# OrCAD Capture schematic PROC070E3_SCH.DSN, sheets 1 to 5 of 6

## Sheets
1 06. HARDWARE SCHEMATICS: title: HARDWARE SCHEMATICS; rev: E3; note: PROC066
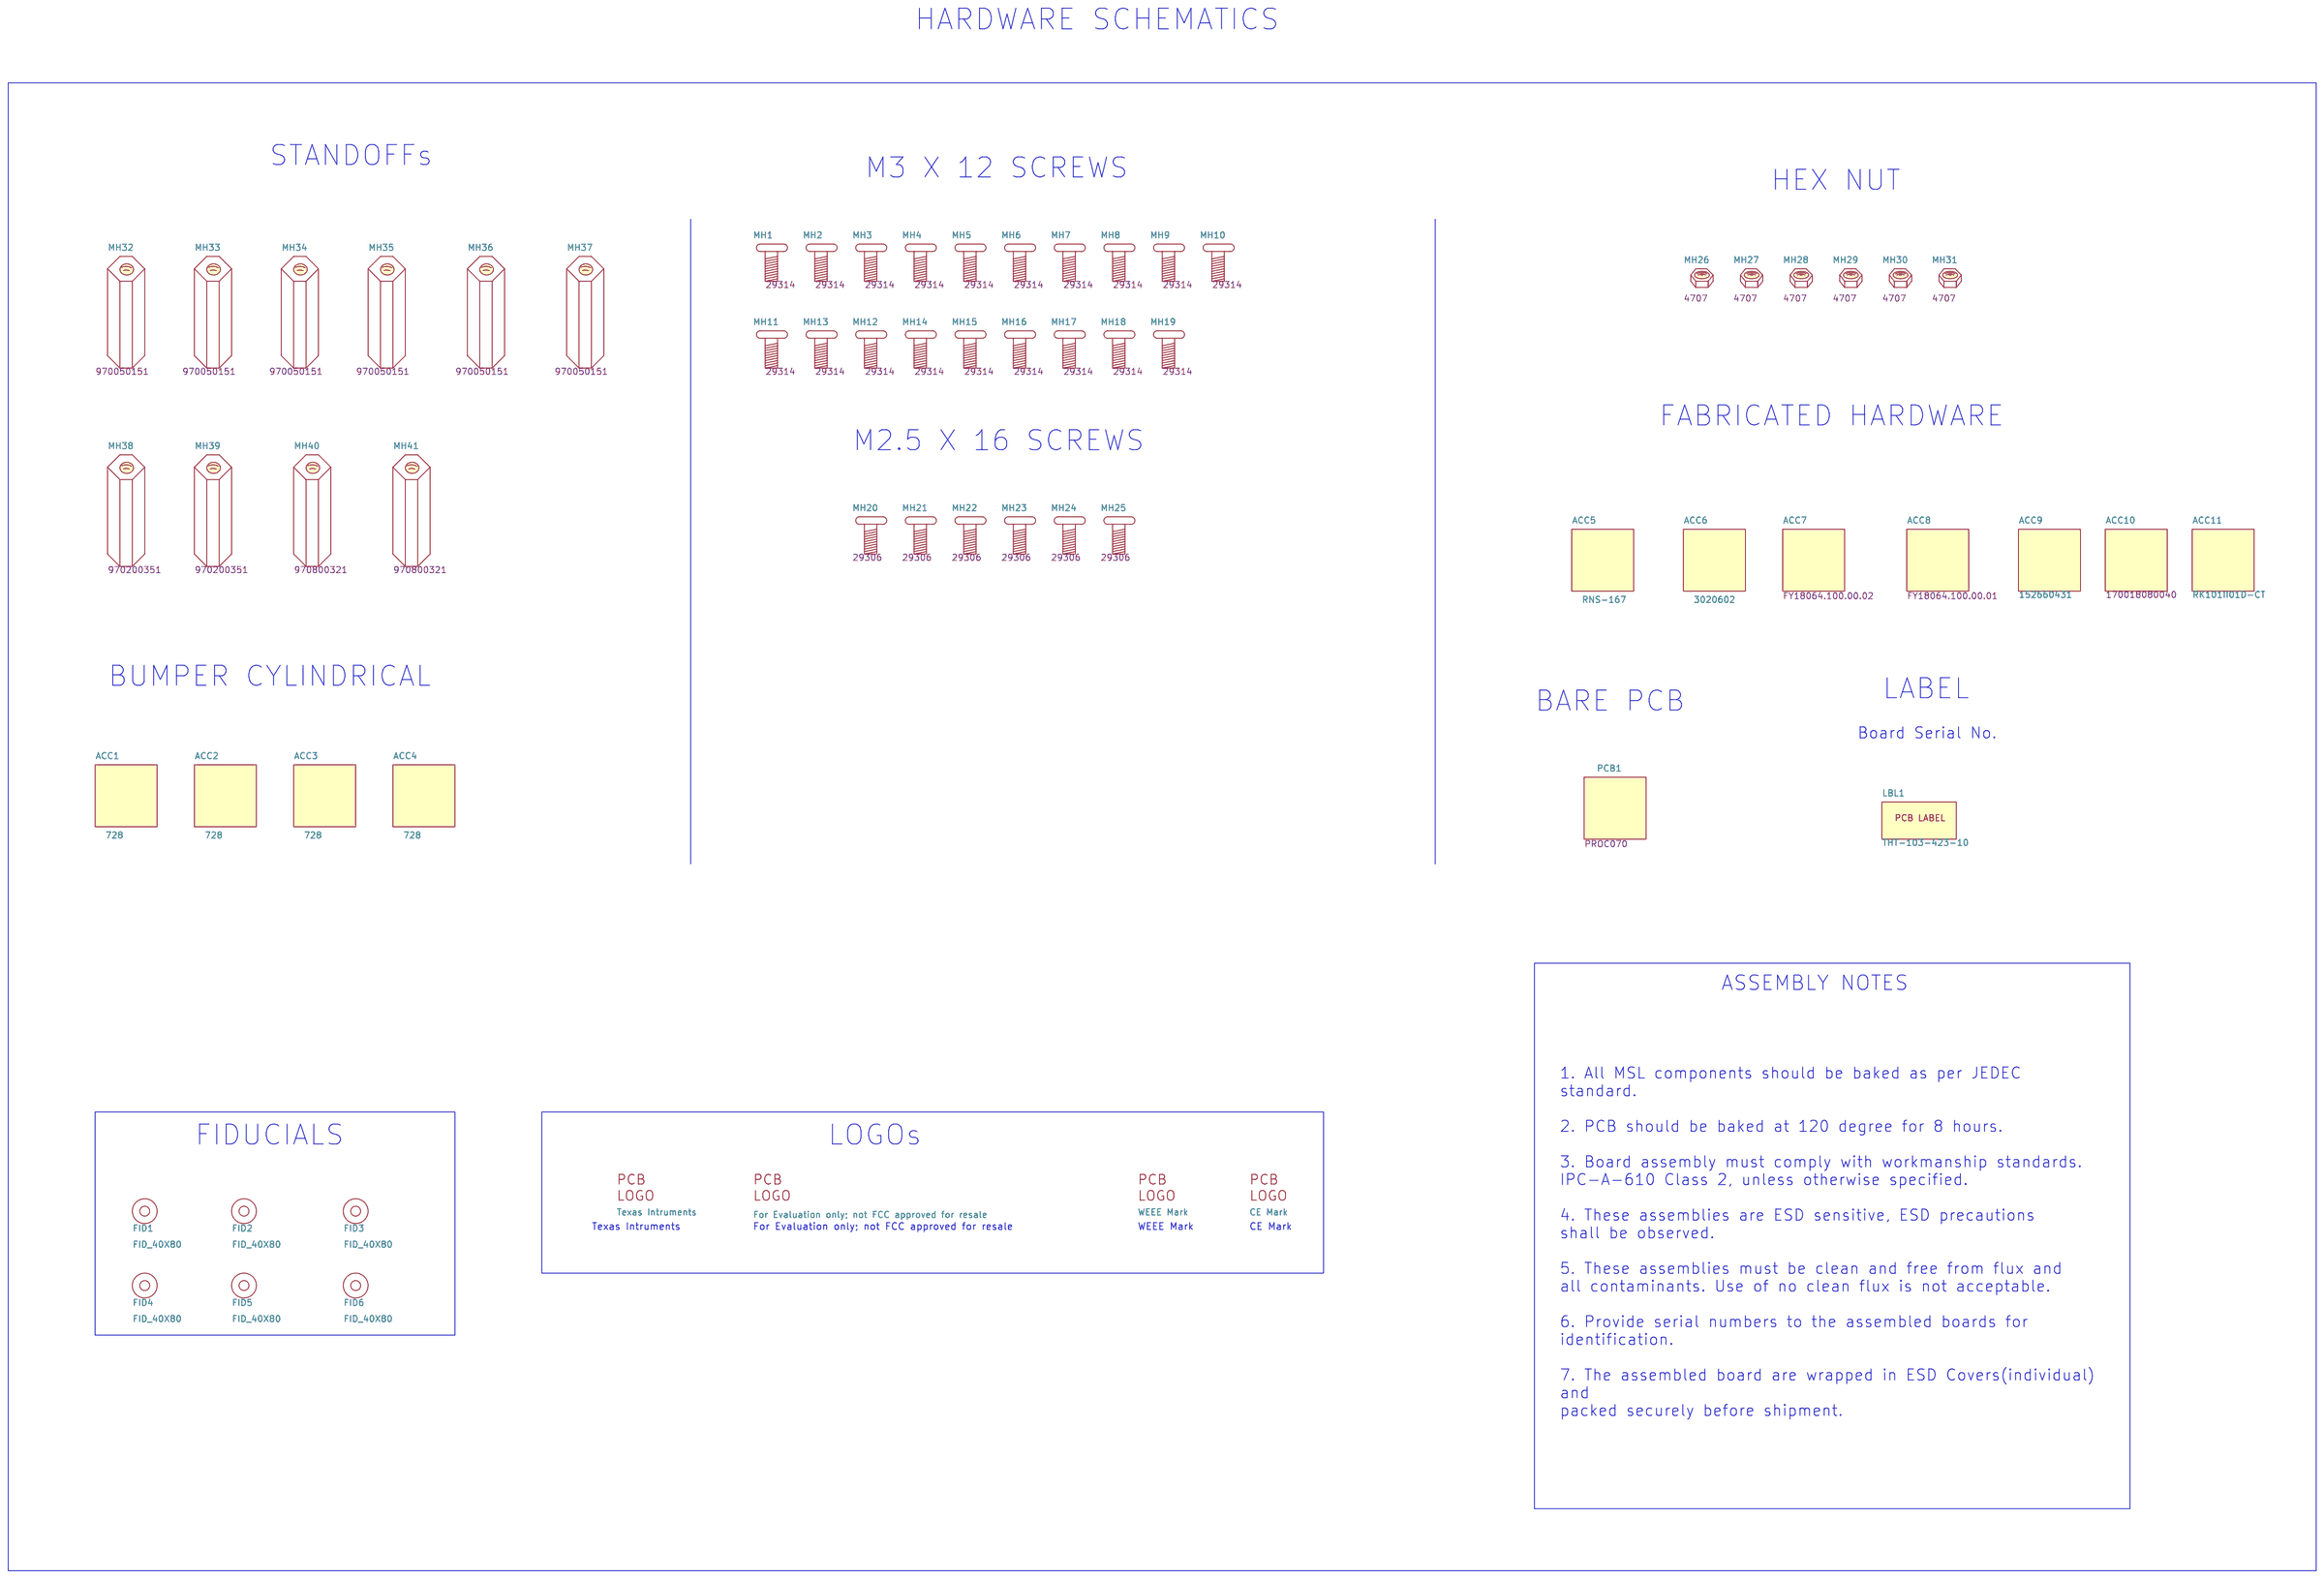
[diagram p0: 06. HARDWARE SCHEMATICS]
2 03. BLOCK DIAGRAM: title: BLOCK DIAGRAM
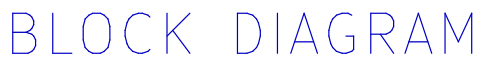
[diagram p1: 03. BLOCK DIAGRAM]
3 02. REVISION HISTORY: title: VERSION HISTORY
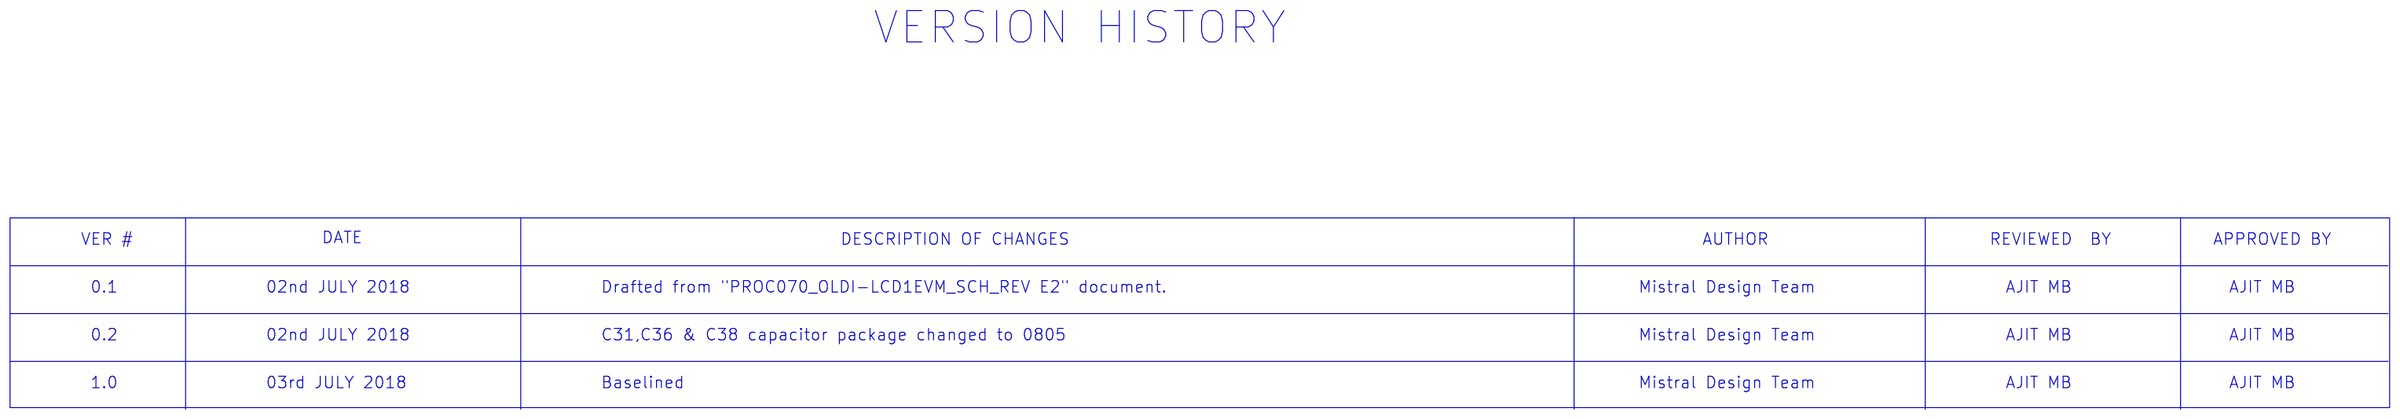
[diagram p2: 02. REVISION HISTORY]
4 01. TABLE OF CONTENTS: title: TABLE OF CONTENTS
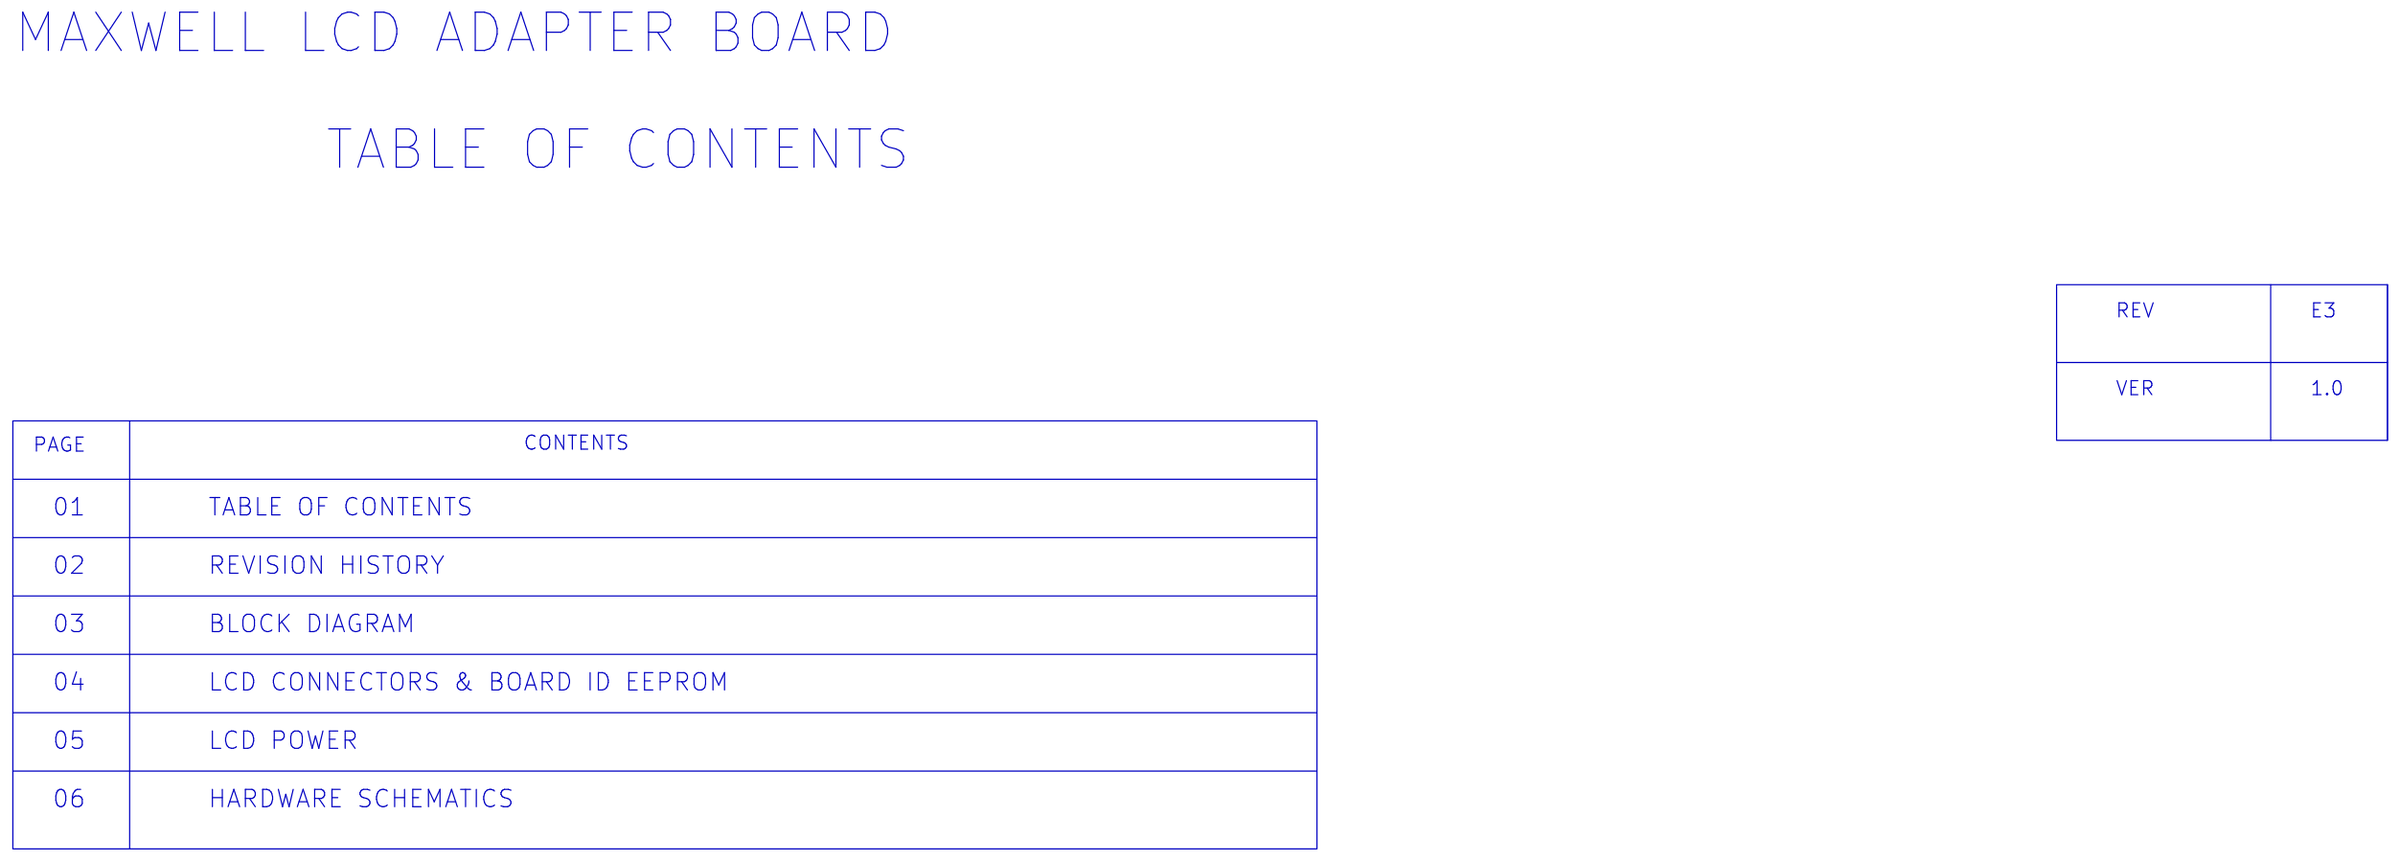
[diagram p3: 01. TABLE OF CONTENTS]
5 04. LCD CONNECTOR & EEPROM: size C; title: LCD CONNECTOR & EEPROM
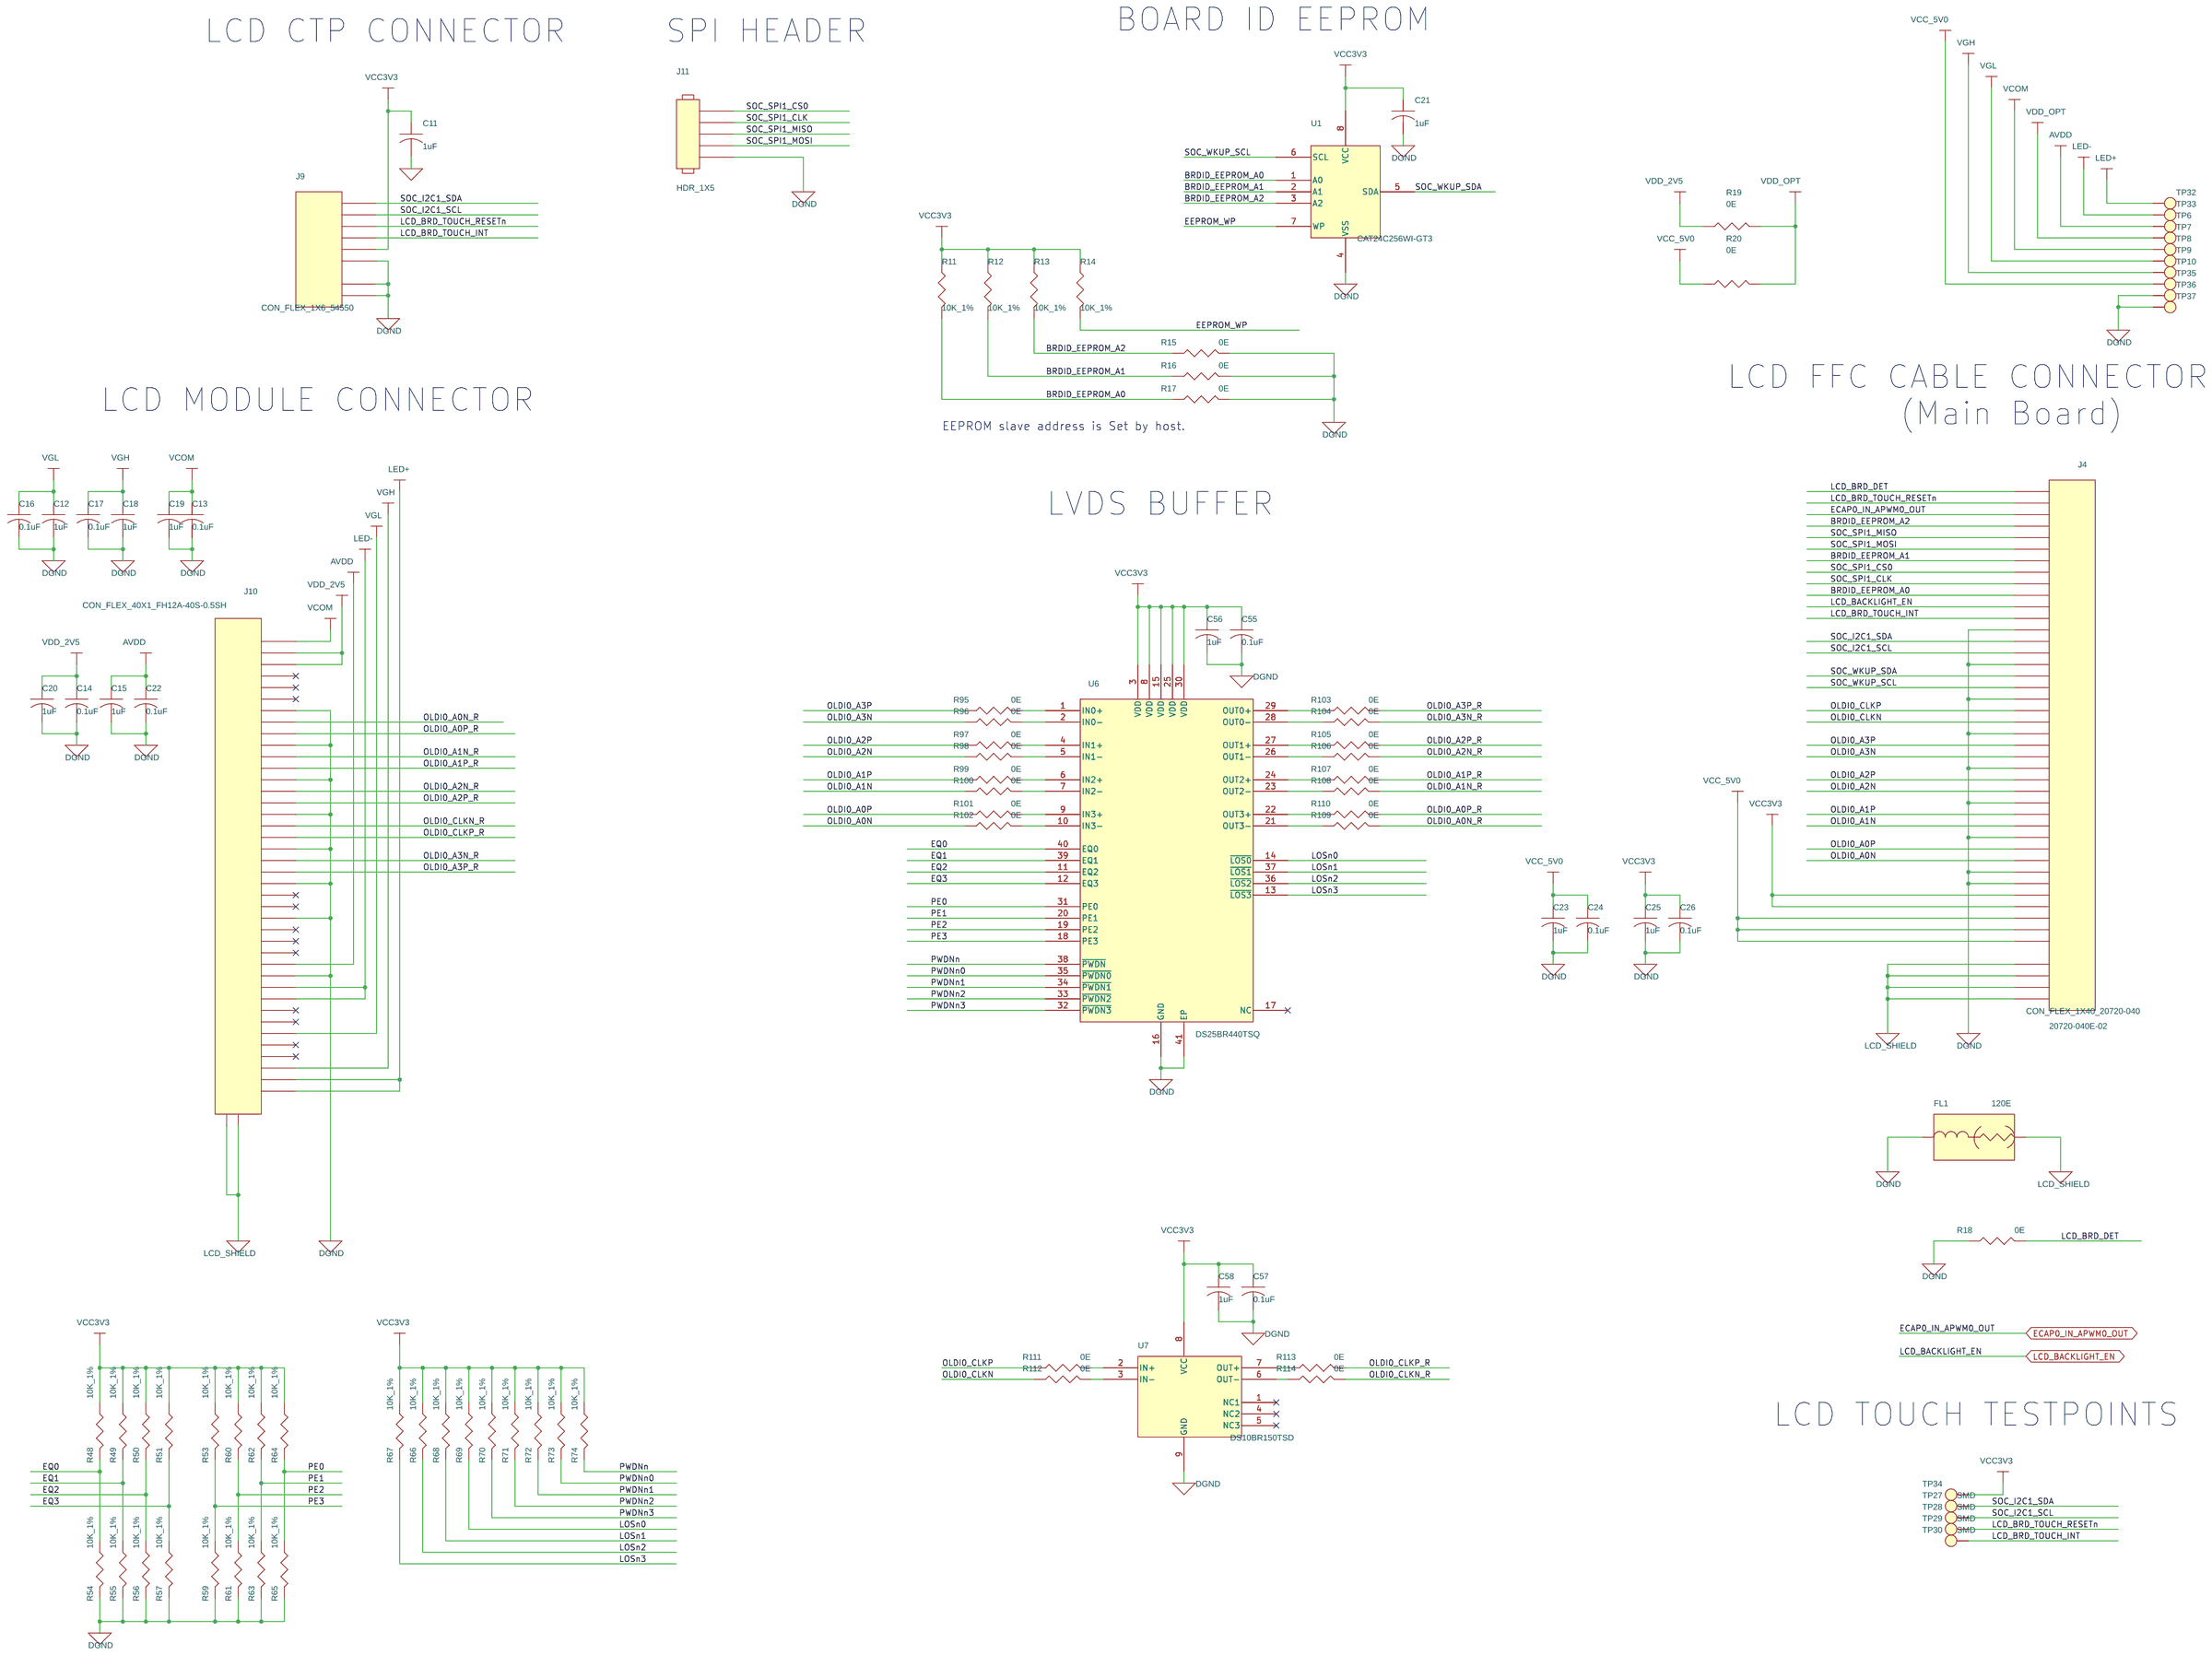
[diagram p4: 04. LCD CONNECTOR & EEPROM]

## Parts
sheet 04. LCD CONNECTOR & EEPROM
C11  1uF  [CAP0402_0-75]
C12  1uF  [CAP0805_1-5]
C13  0.1uF  [CAP0201_0-5]
C14  0.1uF  [CAP0201_0-5]
C15  1uF  [CAP0402_0-75]
C16  0.1uF  [CAP0402_0-75]
C17  0.1uF  [CAP0402_0-75]
C18  1uF  [CAP0805_1-5]
C19  1uF  [CAP0402_0-75]
C20  1uF  [CAP0402_0-75]
C21  1uF  [CAP0402_0-75]
C22  0.1uF  [CAP0201_0-5]
C23  1uF  [CAP0402_0-75]
C24  0.1uF  [CAP0201_0-5]
C25  1uF  [CAP0402_0-75]
C26  0.1uF  [CAP0201_0-5]
C55  0.1uF  [CAP0201_0-5]
C56  1uF  [CAP0402_0-75]
C57  0.1uF  [CAP0201_0-5]
C58  1uF  [CAP0402_0-75]
FL1  120E  [EMIFIL_BLM15A_0402_0-6]
J4  CON_FLEX_1X40_20720-040  [CON_FLEX1X40_20720-040_S_R_S_2]
J9  CON_FLEX_1X6_54550  [CON_FLEX1X6_54550-0671_S_R_S_1-3]
J10  CON_FLEX_40X1_FH12A-40S-0.5SH  [CON_FLEX40X1_FH12A_S_R_S]
J11  HDR_1X5  [HDR_5X1_100_S_T_11-2]
R11  10K_1%  [RES0402_0-5]
R12  10K_1%  [RES0402_0-5]
R13  10K_1%  [RES0402_0-5]
R14  10K_1%  [RES0402_0-5]
R15  0E  [RES0402_0-5]
R16  0E  [RES0402_0-5]
R17  0E  [RES0402_0-5]
R18  0E  [RES0402_0-5]
R19  0E  [RES0402_0-5]
R20  0E  [RES0402_0-5]
R48  10K_1%  [RES0402_0-5]
R49  10K_1%  [RES0402_0-5]
R50  10K_1%  [RES0402_0-5]
R51  10K_1%  [RES0402_0-5]
R53  10K_1%  [RES0402_0-5]
R54  10K_1%  [RES0402_0-5]
R55  10K_1%  [RES0402_0-5]
R56  10K_1%  [RES0402_0-5]
R57  10K_1%  [RES0402_0-5]
R59  10K_1%  [RES0402_0-5]
R60  10K_1%  [RES0402_0-5]
R61  10K_1%  [RES0402_0-5]
R62  10K_1%  [RES0402_0-5]
R63  10K_1%  [RES0402_0-5]
R64  10K_1%  [RES0402_0-5]
R65  10K_1%  [RES0402_0-5]
R66  10K_1%  [RES0402_0-5]
R67  10K_1%  [RES0402_0-5]
R68  10K_1%  [RES0402_0-5]
R69  10K_1%  [RES0402_0-5]
R70  10K_1%  [RES0402_0-5]
R71  10K_1%  [RES0402_0-5]
R72  10K_1%  [RES0402_0-5]
R73  10K_1%  [RES0402_0-5]
R74  10K_1%  [RES0402_0-5]
R95  0E  [RES0201_0-5]
R96  0E  [RES0201_0-5]
R97  0E  [RES0201_0-5]
R98  0E  [RES0201_0-5]
R99  0E  [RES0201_0-5]
R100  0E  [RES0201_0-5]
R101  0E  [RES0201_0-5]
R102  0E  [RES0201_0-5]
R103  0E  [RES0201_0-5]
R104  0E  [RES0201_0-5]
R105  0E  [RES0201_0-5]
R106  0E  [RES0201_0-5]
R107  0E  [RES0201_0-5]
R108  0E  [RES0201_0-5]
R109  0E  [RES0201_0-5]
R110  0E  [RES0201_0-5]
R111  0E  [RES0201_0-5]
R112  0E  [RES0201_0-5]
R113  0E  [RES0201_0-5]
R114  0E  [RES0201_0-5]
TP6  THRU HOLE  [TP_40X65]
TP7  THRU HOLE  [TP_40X65]
TP8  THRU HOLE  [TP_40X65]
TP9  THRU HOLE  [TP_40X65]
TP10  THRU HOLE  [TP_40X65]
TP27  SMD  [TP50_SMD]
TP28  SMD  [TP50_SMD]
TP29  SMD  [TP50_SMD]
TP30  SMD  [TP50_SMD]
TP32  THRU HOLE  [TP_40X65]
TP33  THRU HOLE  [TP_40X65]
TP34  THRU HOLE  [TP_40X65]
TP35  THRU HOLE  [TP_40X65]
TP36  THRU HOLE  [TP_40X65]
TP37  THRU HOLE  [TP_40X65]
U1  CAT24C256WI-GT3  [SOIC8_1-8]
U6  DS25BR440TSQ  [QFN40_19-68_240X240_0-8]
U7  DS10BR150TSD  [DFN8_19-68_120X120_0-8]
sheet 06. HARDWARE SCHEMATICS
ACC1  728  [NA]
ACC2  728  [NA]
ACC3  728  [NA]
ACC4  728  [NA]
ACC5  RNS-167  [NA]
ACC6  3020602  [NA]
ACC7  FY18064.100.00.01  [NA]
ACC8  FY18064.100.00.01  [NA]
ACC9  152660431  [NA]
ACC10  NA  [NA]
ACC11  RK101II01D-CT  [NA]
FID1  FID_40X80  [FID_40X80]
FID2  FID_40X80  [FID_40X80]
FID3  FID_40X80  [FID_40X80]
FID4  FID_40X80  [FID_40X80]
FID5  FID_40X80  [FID_40X80]
FID6  FID_40X80  [FID_40X80]
LBL1  THT-103-423-10  [NA]
Logo1  Texas Intruments  [TI_Stacked_Overlay_Small]
Logo2  For Evaluation only; not FCC approved for resale  [FCC_disclaimer]
Logo3  WEEE Mark  [TI_Stacked_Overlay_Small]
Logo4  CE Mark  [TI_Stacked_Overlay_Small]
MH1  PAN HEAD_M3 X 12  [NA]
MH2  PAN HEAD_M3 X 12  [NA]
MH3  PAN HEAD_M3 X 12  [NA]
MH4  PAN HEAD_M3 X 12  [NA]
MH5  PAN HEAD_M3 X 12  [NA]
MH6  PAN HEAD_M3 X 12  [NA]
MH7  PAN HEAD_M3 X 12  [NA]
MH8  PAN HEAD_M3 X 12  [NA]
MH9  PAN HEAD_M3 X 12  [NA]
MH10  PAN HEAD_M3 X 12  [NA]
MH11  PAN HEAD_M3 X 12  [NA]
MH12  PAN HEAD_M3 X 12  [NA]
MH13  PAN HEAD_M3 X 12  [NA]
MH14  PAN HEAD_M3 X 12  [NA]
MH15  PAN HEAD_M3 X 12  [NA]
MH16  PAN HEAD_M3 X 12  [NA]
MH17  PAN HEAD_M3 X 12  [NA]
MH18  PAN HEAD_M3 X 12  [NA]
MH19  PAN HEAD_M3 X 12  [NA]
MH20  PAN HEAD_M2.5 X 16  [NA]
MH21  PAN HEAD_M2.5 X 16  [NA]
MH22  PAN HEAD_M2.5 X 16  [NA]
MH23  PAN HEAD_M2.5 X 16  [NA]
MH24  PAN HEAD_M2.5 X 16  [NA]
MH25  PAN HEAD_M2.5 X 16  [NA]
MH26  HEX NUT_M2.5  [NA]
MH27  HEX NUT_M2.5  [NA]
MH28  HEX NUT_M2.5  [NA]
MH29  HEX NUT_M2.5  [NA]
MH30  HEX NUT_M2.5  [NA]
MH31  HEX NUT_M2.5  [NA]
MH32  HEX SPACER_M2.5 X 5  [NA]
MH33  HEX SPACER_M2.5 X 5  [NA]
MH34  HEX SPACER_M2.5 X 5  [NA]
MH35  HEX SPACER_M2.5 X 5  [NA]
MH36  HEX SPACER_M2.5 X 5  [NA]
MH37  HEX SPACER_M2.5 X 5  [NA]
MH38  HEX SPACER_M3 X 20  [NA]
MH39  HEX SPACER_M3 X 20  [NA]
MH40  HEX SPACER_M3 X 80  [NA]
MH41  HEX SPACER_M3 X 80  [NA]
PCB1  AM6x LCD ADAPTER CARD  [NA]

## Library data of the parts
C11 C15 C19-C21 C23 C25 C56 C58 = CAP: CAP CERAMIC 1uF 16V 10% X5R 0402; Chkd/date: MANIRAJA/210817; Crtd /date: MANIRAJA/210817; Custom_Duty: 15%; Customs_HS_Code: 85322990; Distributor_name: DIGIKEY; Distributor_part_number: 587-3709-1-ND; Height: 0.55MM; Mfr_name: TAIYO YUDEN; Mfr_part_number: EMK105BJ105KVHF; Mistral Part No: 120011050002-R; Package: 0402; Part_type: CAPACITORS\CERAMIC; Project: TI_RF_DC CARD; RoHS: RoHS; Temperature: -55°C+85°C; Tolerance: 10%; Voltage: 16V; Wattage: NA; Weight: 0.65mg; Datasheet: Y:\MIS_DATABASE\DATASHEETS\CAPACITORS\EMK105BJ105KVHF.PDF
C12 C18 = CAP: CAP CERAMIC 1uF 50V 10% X7R 0805; Chkd/date: MANIRAJA/130617; Crtd /date: MAZHAR/190111; Custom_Duty: 15%; Customs_HS_Code: 85322990; Distributor_name: DIGIKEY; Distributor_part_number: 490-4736-1-ND; Height: 1.35MM; Mfr_name: MURATA; Mfr_part_number: GRM21BR71H105KA12L; Mistral Part No: 120011010018-R; Package: 0805; Part_type: CAPACITORS\CERAMIC; Project: ITS-PWR_CARD; RoHS: RoHS; Temperature: -55°C+125°C; Tolerance: 10%; Voltage: 50V; Wattage: NA; Weight: 6mg; Datasheet: Y:\MIS_DATABASE\DATASHEETS\CAPACITORS\GRM21BR71H105KA12.PDF
C13 C14 C22 C24 C26 C55 C57 = CAP: CAP CERAMIC 0.1uF 16V 10% X5R 0201; Chkd/date: VASANTHA/140217; Crtd /date: MANIRAJA/140217; Custom_Duty: 15%; Customs_HS_Code: 85322990; Distributor_name: DIGIKEY; Distributor_part_number: 311-1597-1-ND; Height: 0.33MM; Mfr_name: YAGEO AMERICA; Mfr_part_number: CC0201KRX5R7BB104; Mistral Part No: 120009030072-R; Package: 0201; Part_type: CAPACITORS\CERAMIC; Project: GOLDEN-I LITE; RoHS: RoHS; Temperature: -55°C+85°C; Tolerance: 10%; Voltage: 16V; Wattage: NA; Weight: 0.17mg; Datasheet: Y:\MIS_DATABASE\DATASHEETS\CAPACITORS\CC-SERIES.PDF
C16 C17 = CAP: CAP CERAMIC 0.1uF 50V 10% X7R 0402; Chkd/date: VASANTHA/281216; Crtd /date: CHAITHANYA/051011; Custom_Duty: 15%; Customs_HS_Code: 85322990; Distributor_name: DIGIKEY; Distributor_part_number: 445-5932-1-ND; Footprint Path: Y:\MIS_DATABASE\Library\ALTIUM_TOOL\PCB_FOOTPRINTS\Altium_Footprint_Lib.PcbLib; Height: 0.55MM; Library Path: Y:\MIS_DATABASE\Library\ALTIUM_TOOL\SCHEMATICS_PARTS\MS_DISCRETE_Library.schlib; Mfr_name: TDK CORPORATION; Mfr_part_number: C1005X7R1H104K; Mistral Part No: 120011100014-R; Package: 0402; Part_type: CAPACITORS\CERAMIC; Project: VP-4000-BASE-BOARD; RoHS: RoHS; Temperature: -55°C+125°C; Tolerance: 10%; Voltage: 50V; Wattage: NA; Weight: 0.65mg; Datasheet: Y:\MIS_DATABASE\DATASHEETS\CAPACITORS\C1005X7.PDF
FL1 = EMIFILTER_IND: FERRITE CHIP 120E 1.3A 0402; Chkd/date: VASANTHA/010117; Crtd /date: CHAITHANYA/150312; Custom_Duty: 24%; Customs_HS_Code: 85437099; Distributor_name: DIGIKEY; Distributor_part_number: 490-5203-1-ND; Footprint Path: Y:\MIS_DATABASE\Library\ALTIUM_TOOL\PCB_FOOTPRINTS\Altium_Footprint_Lib.PcbLib; Height: 0.55MM; Library Path: Y:\MIS_DATABASE\Library\ALTIUM_TOOL\SCHEMATICS_PARTS\MS_FILTER_Library.schlib; Mfr_name: MURATA; Mfr_part_number: BLM15PD121SN1; Mistral Part No: 130012030043-R; Package: 0402; Part_type: MISC\FILTER; Project: GEN_3-8; RoHS: RoHS; Temperature: -55°C+125°C; Tolerance: 25%; Voltage: NA; Wattage: NA; Weight: 0.65mg; Datasheet: Y:\MIS_DATABASE\DATASHEETS\DISCRETES\INDUCTORS\BLM18K-SERIES.PDF
J4 = CON_FLEX_40X1_SH4: CON FPC 1X40 0.50MM PITCH RT SMD; Chkd/date: MANIRAJA/121017; Crtd /date: MANIRAJA/121017; Custom_Duty: 24%; Customs_HS_Code: 85369090; Distributor_name: NA; Distributor_part_number: NA; Height: 2.00MM; Mfr_name: IPEX; Mfr_part_number: 20720-040E-02; Mistral Part No: 150017100021-R; Package: SMD; Part_type: CONNECTOR\FPC; Project: TI_MAXIE_CPB; RoHS: RoHS; Temperature: -40°C+105°C; Tolerance: NA; Voltage: NA; Wattage: NA; Weight: NA; Datasheet: Y:\MIS_DATABASE\DATASHEETS\CONNECTORS\20720-0XX.PDF
J9 = CON_FLEX_6X1_SH2: CON FPC 1X6 0.50MM PITCH TOP RT SMD; Chkd/date: MANIRAJA/131117; Crtd /date: MANIRAJA/131117; Custom_Duty: 24%; Customs_HS_Code: 85369090; Distributor_name: DIGIKEY; Distributor_part_number: WM6789CT-ND; Height: 1.30MM; Mfr_name: MOLEX; Mfr_part_number: 54550-0671; Mistral Part No: 150017110019-R; Package: SMD; Part_type: CONNECTOR\FPC; Project: TI_SVB_MAXWELL_LCD-AB; RoHS: RoHS; Temperature: -20°C+85°C; Tolerance: NA; Voltage: NA; Wattage: NA; Weight: 49mg; Datasheet: Y:\MIS_DATABASE\DATASHEETS\CONNECTORS\54550-042.PDF
J10 = CON_FLEX_40X1_FH12A-40S-0.5SH: CON FPC 40X1 0.50MM PITCH RT TOP SMD; Chkd/date: SHREESHAIL/201106; Crtd /date: MAZHAR/171106; Custom_Duty: 24%; Customs_HS_Code: 85369090; Distributor_name: DIGIKEY; Distributor_part_number: HFK40CT-ND; Height: 2.00MM; Mfr_name: HIROSE ELECTRIC EUROPE; Mfr_part_number: FH12A-40S-0.5SH(55); Mistral Part No: 150009030176-R; Package: SMD; Part_type: CONNECTOR\FPC; Project: PMP LCD BOARD; Remarks: CON_FLEX40X1_FH12A_S_R_S_PMP take this footprint for PMP LCD BOARD/ROHS INFORMATION ADDED(BAVISH/270911)Mistral part# updated with -R.; Datasheet: Y:\MIS_DATABASE\DATASHEETS\CONNECTORS\FH12SERIES.PDF
J11 = HEADER_5X1: CON HDR 1X5 2.54MM PITCH ST TH; Chkd/date: VASANTHA/310117; Crtd /date: MAZHAR/280405; Custom_Duty: 24%; Customs_HS_Code: 85369090; Distributor_name: DIGIKEY; Distributor_part_number: WM4003-ND; Footprint Path: Y:\MIS_DATABASE\Library\ALTIUM_TOOL\PCB_FOOTPRINTS\Altium_Footprint_Lib.PcbLib; Height: 11.17MM; Library Path: Y:\MIS_DATABASE\Library\ALTIUM_TOOL\SCHEMATICS_PARTS\MS_CONNECTOR_Library.schlib; Mfr_name: MOLEX; Mfr_part_number: 22-03-2051; Mistral Part No: 150009030262-R; Package: THRU-HOLE; Part_type: CONNECTOR\HEADERS; Project: HSWD; RoHS: RoHS; Temperature: NA; Tolerance: NA; Voltage: NA; Wattage: NA; Weight: 343mg; Datasheet: Y:\MIS_DATABASE\DATASHEETS\CONNECTORS\MOLEX022032021.PDF
R11-R14 R48-R51 R53-R57 R59-R74 = RESISTOR: RES 10K 1/10W 1% 0402; Chkd/date: MANIRAJA/190218; Crtd /date: NAVEED/280515; Custom_Duty: 15%; Customs_HS_Code: 85332119; Distributor_name: DIGIKEY; Distributor_part_number: P10.0KLCT-ND; Footprint Path: Y:\MIS_DATABASE\Library\ALTIUM_TOOL\PCB_FOOTPRINTS\Altium_Footprint_Lib.PcbLib; Height: 0.40MM; Library Path: Y:\MIS_DATABASE\Library\ALTIUM_TOOL\SCHEMATICS_PARTS\MS_DISCRETE_Library.schlib; Mfr_name: PANASONIC-ECG; Mfr_part_number: ERJ-2RKF1002X; Mistral Part No: 110015050015-R; Package: 0402; Part_type: RESISTORS\FIXED; Project: DLRL NARROW BAND; RoHS: RoHS; Temperature: -55°C+155°C; Tolerance: 1%; Voltage: NA; Wattage: 1/10W; Weight: 0.8mg; Datasheet: Y:\MIS_DATABASE\DATASHEETS\RESISTORS\PAN-ERJSER_NOV17.PDF
R15-R20 = RESISTOR: RES 0E 1/16W 0402; Chkd/date: VASANTHA/201216; Crtd /date: MUDDU/190810; Custom_Duty: 15%; Customs_HS_Code: 85332119; Distributor_name: DIGIKEY; Distributor_part_number: 541-0.0JCT-ND; Footprint Path: Y:\MIS_DATABASE\Library\ALTIUM_TOOL\PCB_FOOTPRINTS\Altium_Footprint_Lib.PcbLib; Height: 0.40MM; Library Path: Y:\MIS_DATABASE\Library\ALTIUM_TOOL\SCHEMATICS_PARTS\MS_DISCRETE_Library.schlib; Mfr_name: VISHAY; Mfr_part_number: CRCW04020000Z0ED; Mistral Part No: 110010080019-P; Package: 0402; Part_type: RESISTORS\FIXED; Project: PB_BUGBASE; RoHS: Pb-Free; Temperature: -55°C+155°C; Tolerance: NA; Voltage: NA; Wattage: 1/16W; Weight: 0.65g/1000pcs; Datasheet: Y:\MIS_DATABASE\DATASHEETS\RESISTORS\CRCW0603.PDF
R95-R114 = RESISTOR: RES 0E 1/20W JUMPER 0201; Chkd/date: VASANTHA/061216; Crtd /date: MAZHAR/040505; Custom_Duty: 15%; Customs_HS_Code: 85332119; Distributor_name: DIGIKEY; Distributor_part_number: P0.0AGCT-ND; Footprint Path: Y:\MIS_DATABASE\Library\ALTIUM_TOOL\PCB_FOOTPRINTS\Altium_Footprint_Lib.PcbLib; Height: 0.26MM; Mfr_name: PANASONIC-ECG; Mfr_part_number: ERJ-1GE0R00C; Mistral Part No: 110009030078-R; Package: 0201; Part_type: RESISTORS\FIXED; Project: HS100RD; RoHS: RoHS; Temperature: -55°C+125°C; Tolerance: NA; Voltage: NA; Wattage: 1/20W; Weight: 0.15g/1000pcs; Datasheet: Y:\MIS_DATABASE\DATASHEETS\RESISTORS\ERJ-1G.PDF
TP6-TP10 TP32-TP37 = TESTPOINT: TESTPOINT 1.0MM DRILL PTH; Chkd/date: MAZHAR/271211; Crtd /date: SHREESHAIL/041005; Distributor_name: NA; Distributor_part_number: NA; Height: NA; Mfr_name: LOCAL; Mistral Part No: 130009030938; Package: THRU-HOLE; Part_type: MISC\TESTPOINT; Project: HSE; Datasheet: NA
TP27-TP30 = TESTPOINT: TESTPOINT 50 SMD; Chkd/date: SHREESHAIL/270407; Crtd /date: MAZHAR/260407; Distributor_name: NA; Distributor_part_number: NA; Height: NA; Mfr_name: LOCAL; Mistral Part No: 130009030931; Part_type: MISC\TESTPOINT; Project: MICODER-1
U1 = CAT24C256WI-GT3_SOIC8: IC 256K I2C CMOS SERIAL EEPROM SOIC8; Chkd/date: MANIRAJA/130617; Crtd /date: MUDDU/270510; Custom_Duty: 15%; Customs_HS_Code: 85423100; Distributor_name: DIGIKEY; Distributor_part_number: CAT24C256WI-GT3-ND; Height: 1.75MM; Mfr_name: ON SEMICONDUCTOR; Mistral Part No: 141110050004-R; Package: SOIC8; Part_type: ICS\DIGITAL\MEMORY; Project: CENTAURUS; RoHS: RoHS; Temperature: -40°C+85°C; Tolerance: NA; Voltage: NA; Wattage: NA; Weight: 540mg; Datasheet: Y:\MIS_DATABASE\DATASHEETS\ICS\MEMORY\CAT24C256WI.PDF
U6 = DS25BR440TSQ_WQFN40: IC 3.125GBPS QUAD LVDS BUFFER WITH TRANSCEIVER EQUALIZATION WQFN40; Chkd/date: MANIRAJA/020118; Crtd /date: MANIRAJA/020118; Custom_Duty: 15%; Customs_HS_Code: 85423100; Distributor_name: DIGIKEY; Distributor_part_number: DS25BR440TSQ/NOPBCT-ND; Height: 0.80MM; Mfr_name: TEXAS INSTRUMENTS; Mfr_part_number: DS25BR440TSQ/NOPB; Mistral Part No: 141018010001-R; Package: WQFN40; Part_type: ICS\DIGITAL\COMBINATIONAL; Project: TI_SVB_MAXWELL_LCD-AB; RoHS: RoHS; Temperature: -40°C+85°C; Tolerance: NA; Voltage: NA; Wattage: NA; Weight: 93.7mg; Datasheet: Y:\MIS_DATABASE\DATASHEETS\ICS\DIGITAL\COMBINATIONAL\DS25BR440TSQ.PDF
U7 = DS10BR150TSD_WSON8: IC 1GBPS LVDS BUFFER/REPEATER WSON8; Chkd/date: MANIRAJA/040118; Crtd /date: ALVY/040118; Custom_Duty: 15%; Customs_HS_Code: 85423100; Distributor_name: DIGIKEY; Distributor_part_number: DS10BR150TSD/NOPBCT-ND; Height: 0.80MM; Mfr_name: TEXAS INSTRUMENTS; Mfr_part_number: DS10BR150TSD/NOPB; Mistral Part No: 141018010002-R; Package: WSON8; Part_type: ICS\DIGITAL\COMBINATIONAL; Project: TI_SVB_MAXWELL_LCD-AB; RoHS: RoHS; Temperature: -40°C+85°C; Tolerance: NA; Voltage: NA; Wattage: NA; Weight: NA; Datasheet: Y:\MIS_DATABASE\DATASHEETS\ICS\DIGITAL\COMBINATIONAL\DS10BR150.PDF
ACC1-ACC4 = ACCESSORY: ACCESSORIE RECESSED BUMPER 19.05MM DIA; Chkd/date: MANIRAJA/110718; Crtd /date: MANIRAJA/110718; Distributor_name: DIGIKEY; Distributor_part_number: 36-728-ND; Mfr_name: KEYSTONE; Mistral Part No: 160018070042-R; Part_type: ACCESSORIES; Project: TI_MAXIE_CPB; RoHS: RoHS; Weight: 2042mg; Datasheet: Y:\MIS_DATABASE\DATASHEETS\MISC\ACCESSORIES\728.PDF
ACC5 = ACCESSORY: ACCESSORIE NYLON STRAP WITH HOLES BLACK 30M LENGTH; Chkd/date: MANIRAJA/200318; Crtd /date: MANIRAJA/200318; Distributor_name: DIGIKEY; Distributor_part_number: RPC2078-ND; Footprint Path: Y:\MIS_DATABASE\Library\ALTIUM_TOOL\PCB_FOOTPRINTS\Altium_Footprint_Lib.PcbLib; Library Path: Y:\MIS_DATABASE\Library\ALTIUM_TOOL\SCHEMATICS_PARTS\MS_MECHANICAL_Library.schlib; Mfr_name: RICHO; Mistral Part No: 160018030008-R; Part_type: ACCESSORIES; Project: TI_SVB_MAXWELL_LCD-AB; RoHS: RoHS; Datasheet: Y:\MIS_DATABASE\DATASHEETS\MISC\ACCESSORIES\RNS-167.PDF
ACC6 = ACCESSORY: ACCESSORIE WE-LT CONDUCTIVE SHIELDING GASKET 1000 X 6 X 2MM; Chkd/date: MANIRAJA/040918; Crtd /date: MANIRAJA/040918; Distributor_name: DIGIKEY; Distributor_part_number: 732-10222-ND; Mfr_name: WURTH ELECTRONICS; Mistral Part No: 160018090003-R; Part_type: ACCESSORIES; Project: TI_MAXIE_CPB; RoHS: RoHS; Temperature: -40°C+85°C; Datasheet: Y:\MIS_DATABASE\DATASHEETS\MISC\ACCESSORIES\3020602.PDF
ACC7 = ACCESSORY: ACCESSORIE MS_TI_MAXWELL_LCD_FRONT_PLATE_V0.1; Chkd/date: MANIRAJA/160218; Crtd /date: MANIRAJA/160218; Mfr_name: LOCAL; Mfr_part_number: FY18064.100.00.02; Mistral Part No: 160018020066; Part_type: MECHANICAL; Project: TI_MAXWELL_LCD; Datasheet: Y:\MIS_DATABASE\DATASHEETS\MISC\MECHANICAL\FY18064.100.00.02.PDF
ACC8 = ACCESSORY: ACCESSORIE MS_TI_MAXWELL_LCD_CLAMP_V0.1; Chkd/date: MANIRAJA/160218; Crtd /date: MANIRAJA/160218; Mfr_name: LOCAL; Mistral Part No: 160018020067; Part_type: MECHANICAL; Project: TI_MAXWELL_LCD; Datasheet: Y:\MIS_DATABASE\DATASHEETS\MISC\MECHANICAL\FY18064.100.00.01.PDF
ACC9 = ACCESSORY: ACCESSORIE CABLE 40POS 0.50MM PITCH FFC JUMPER 102MM LENGTH; Chkd/date: MANIRAJA/310118; Crtd /date: MANIRAJA/310118; Distributor_name: DIGIKEY; Distributor_part_number: WM10534-ND; Mfr_name: MOLEX; Mistral Part No: 170018010007-R; Part_type: CABLE\ACCESSORIES; Project: TI_SVB_MAXWELL_LCD-AB; RoHS: RoHS; Temperature: -40°C+105°C; Weight: 1.345g; Datasheet: Y:\MIS_DATABASE\DATASHEETS\CABLES\152660431.PDF
ACC10 = ACCESSORY: ACCESSORIE CABLE OFFIPX18001N SHIELDED FFC FOR EVAFLEX5-VS 101.6MM LENGTH; Chkd/date: MANIRAJA/240818; Crtd /date: ALVY/240818; Mfr_name: LOCAL; Mistral Part No: 170018080040; Part_type: CABLE\ACCESSORIES; Project: TI_MAXIE_CPB
ACC11 = ACCESSORY: ACCESSORIE LCD MODULE 10.1” TFT 1280X800 PIXELS LED CAPACITIVE TOUCH PANEL; Chkd/date: MANIRAJA/250118; Crtd /date: MANIRAJA/250118; Mfr_name: ROCKTECH; Mistral Part No: 160018010038; Part_type: ACCESSORIES; Project: TI_SVB_MAXWELL_LCD-AB; Temperature: -10°C+60°C; Datasheet: Y:\MIS_DATABASE\DATASHEETS\MISC\ACCESSORIES\RK101II01D.PDF
FID1-FID6 = Fiducial
LBL1 = ACCESSORY_THT-3-423-10: ACCESSORIE 1 WORKHORSE POLYSTER LABLE 0.25" X 1"; Chkd/date: MANIRAJA/270218; Crtd /date: ALVY/260218; Footprint Path: Y:\MIS_DATABASE\Library\ALTIUM_TOOL\PCB_FOOTPRINTS\Altium_Footprint_Lib.PcbLib; Library Path: Y:\MIS_DATABASE\Library\ALTIUM_TOOL\SCHEMATICS_PARTS\MS_MECHANICAL_Library.schlib; Mfr_name: BRADY; Mistral Part No: 160018020185; Part_type: ACCESSORIES; Project: TI_MAXIE_CPB
Logo1 Logo3 Logo4 = TI_Logo
Logo2 = FCC_disclaimer
MH1-MH19 = SCREW_PAN: SLOTTED PAN HEAD SCREW – M3 X 12; Chkd/date: MANIRAJA/230718; Crtd /date: ALVY/230718; Distributor_name: DIGIKEY; Distributor_part_number: 36-29314-ND; Height: 12.00MM; Mfr_name: KEYSTONE; Mfr_part_number: 29314; Mistral Part No: 160018070070-R; Part_type: ACCESSORIES; Project: TI_MAXIE_CPB; RoHS: RoHS; Datasheet: Y:\MIS_DATABASE\DATASHEETS\MISC\MECHANICAL\29314.PDF
MH20-MH25 = SCREW_PAN: PHILLIPS PAN HEAD SCREW - M2.5 X 16 SS-316; Chkd/date: MANIRAJA/200318; Crtd /date: MANIRAJA/200318; Distributor_name: DIGIKEY; Distributor_part_number: 36-29306-ND; Footprint Path: Y:\MIS_DATABASE\Library\ALTIUM_TOOL\PCB_FOOTPRINTS\Altium_Footprint_Lib.PcbLib; Height: 16.00MM; Library Path: Y:\MIS_DATABASE\Library\ALTIUM_TOOL\SCHEMATICS_PARTS\MS_MECHANICAL_Library.schlib; Mfr_name: KEYSTONE; Mfr_part_number: 29306; Mistral Part No: 160018030006-R; Package: SS; Part_type: MECHANICAL\SCREWS; Project: TI_SVB_MAXWELL_LCD-AB; RoHS: RoHS; Datasheet: Y:\MIS_DATABASE\DATASHEETS\MISC\MECHANICAL\29306.PDF
MH26-MH31 = HEX_NUT: M2.5 NUT HEX STEEL; Chkd/date: MANIRAJA/200318; Crtd /date: MANIRAJA/200318; Distributor_name: DIGIKEY; Distributor_part_number: 36-4707-ND; Footprint Path: Y:\MIS_DATABASE\Library\ALTIUM_TOOL\PCB_FOOTPRINTS\Altium_Footprint_Lib.PcbLib; Library Path: Y:\MIS_DATABASE\Library\ALTIUM_TOOL\SCHEMATICS_PARTS\MS_MECHANICAL_Library.schlib; Mfr_name: KEYSTONE; Mfr_part_number: 4707; Mistral Part No: 160018030007-R; Package: SS; Part_type: MECHANICAL\NUT; Project: TI_SVB_MAXWELL_LCD-AB; RoHS: RoHS; Datasheet: Y:\MIS_DATABASE\DATASHEETS\MISC\MECHANICAL\4707.PDF
MH32-MH37 = HEX_SPACER_FF: HEX SPACER FEMALE TO FEMALE M2.5 X 5MM; Chkd/date: MANIRAJA/200318; Crtd /date: MANIRAJA/200318; Distributor_name: DIGIKEY; Distributor_part_number: 732-10519-ND; Footprint Path: Y:\MIS_DATABASE\Library\ALTIUM_TOOL\PCB_FOOTPRINTS\Altium_Footprint_Lib.PcbLib; Height: 5.00MM; Library Path: Y:\MIS_DATABASE\Library\ALTIUM_TOOL\SCHEMATICS_PARTS\MS_MECHANICAL_Library.schlib; Mfr_name: WURTH ELECTRONICS; Mfr_part_number: 970050151; Mistral Part No: 160018030005-R; Package: SS; Part_type: MECHANICAL\SPACER; Project: TI_SVB_MAXWELL_LCD-AB; RoHS: RoHS; Datasheet: Y:\MIS_DATABASE\DATASHEETS\MISC\MECHANICAL\970XXX1.PDF
MH38 MH39 = HEX_SPACER_FF: HEX SPACER FEMALE TO FEMALE M3 X 20MM; Chkd/date: MANIRAJA/190218; Crtd /date: MANIRAJA/190218; Distributor_name: DIGIKEY; Distributor_part_number: 732-10595-ND; Footprint Path: Y:\MIS_DATABASE\Library\ALTIUM_TOOL\PCB_FOOTPRINTS\Altium_Footprint_Lib.PcbLib; Height: 20.00MM; Library Path: Y:\MIS_DATABASE\Library\ALTIUM_TOOL\SCHEMATICS_PARTS\MS_MECHANICAL_Library.schlib; Mfr_name: WURTH ELECTRONICS; Mfr_part_number: 970200351; Mistral Part No: 160018020070-R; Package: SS; Part_type: MECHANICAL\SPACER; Project: TI_MAXIE_CPB; RoHS: RoHS; Datasheet: Y:\MIS_DATABASE\DATASHEETS\MISC\MECHANICAL\970XXX1.PDF
MH40 MH41 = HEX_SPACER_FF: HEX SPACER FEMALE TO FEMALE M3 X 80MM; Chkd/date: MANIRAJA/190218; Crtd /date: MANIRAJA/190218; Distributor_name: DIGIKEY; Distributor_part_number: 732-10680-ND; Footprint Path: Y:\MIS_DATABASE\Library\ALTIUM_TOOL\PCB_FOOTPRINTS\Altium_Footprint_Lib.PcbLib; Height: 80.00MM; Library Path: Y:\MIS_DATABASE\Library\ALTIUM_TOOL\SCHEMATICS_PARTS\MS_MECHANICAL_Library.schlib; Mfr_name: WURTH ELECTRONICS; Mfr_part_number: 970800321; Mistral Part No: 160018020069-R; Package: SS; Part_type: MECHANICAL\SPACER; Project: TI_MAXIE_CPB; RoHS: RoHS; Datasheet: Y:\MIS_DATABASE\DATASHEETS\MISC\MECHANICAL\970XXX1.PDF
PCB1 = ACCESSORY_PROC064: ACCESSORIE AM6x LCD ADAPTER CARD; Chkd/date: MANIRAJA/230718; Crtd /date: MANIRAJA/230718; Mfr_name: TEXAS INSTRUMENTS; Mfr_part_number: PROC070; Mistral Part No: FY180106000603; Part_type: ACCESSORIES; Project: TI_MAXIE_CPB

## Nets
AVDD: C15.1 C22.1 J10.29 TP6.1(TP) ; also on sheet 6
DGND: C11.2 C12.2 C13.2 C14.2 C15.2 C16.2 C17.2 C18.2 C19.2 C20.2 C21.2 C22.2 C23.2 C24.2 C25.2 C26.2 C55.2 C56.2 C57.2 C58.2 FL1.1 J4.13 J4.16 J4.19 J4.22 J4.25 J4.28 J4.31 J4.34 J4.35 J9.6 J9.SH1 J9.SH2 J10.7 J10.10 J10.13 J10.16 J10.19 J10.22 J10.25 J10.30 J11.5 R15.2 R16.2 R17.2 R18.1 R54.2 R55.2 R56.2 R57.2 R59.2 R61.2 R63.2 R65.2 TP36.1(TP) TP37.1(TP) U1.4(VSS) U6.16(GND) U6.41(EP) U7.9(GND) ; also on sheet 6
VCC3V3: C11.1 C21.1 C25.1 C26.1 C55.1 C56.1 C57.1 C58.1 J4.36 J4.37 J9.5 R11.1 R12.1 R13.1 R14.1 R48.1 R49.1 R50.1 R51.1 R53.1 R60.1 R62.1 R64.1 R66.1 R67.1 R68.1 R69.1 R70.1 R71.1 R72.1 R73.1 R74.1 TP34.1(TP) U1.8(VCC) U6.3(VDD) U6.8(VDD) U6.15(VDD) U6.25(VDD) U6.30(VDD) U7.8(VCC) ; also on sheet 6
VCC_5V0: C23.1 C24.1 J4.38 J4.39 J4.40 R20.1 TP35.1(TP) ; also on sheet 6
VDD_2V5: C14.1 C20.1 J10.2 J10.3 R19.1 ; also on sheet 6
VDD_OPT: R19.2 R20.2 TP7.1(TP)
BRDID_EEPROM_A0: J4.10 R11.2 R17.1 U1.1(A0)
BRDID_EEPROM_A1: J4.7 R12.2 R16.1 U1.2(A1)
BRDID_EEPROM_A2: J4.4 R13.2 R15.1 U1.3(A2)
ECAP0_IN_APWM0_OUT: J4.3 ; also on sheet 6
EEPROM_WP: R14.2 U1.7(WP)
EQ0: R48.2 R54.1 U6.40(EQ0)
EQ1: R49.2 R55.1 U6.39(EQ1)
EQ2: R50.2 R56.1 U6.11(EQ2)
EQ3: R51.2 R57.1 U6.12(EQ3)
LCD_BACKLIGHT_EN: J4.11 ; also on sheet 6
LCD_BRD_DET: J4.1 R18.2
LCD_BRD_TOUCH_INT: J4.12 J9.4 TP30.1(TP)
LCD_BRD_TOUCH_RESETn: J4.2 J9.3 TP29.1(TP)
LCD_SHIELD: FL1.2 J4.SH1 J4.SH2 J4.SH3 J4.SH4 J10.41 J10.42
LED+: J10.39 J10.40 TP32.1(TP) ; also on sheet 6
LED-: J10.31 J10.32 TP33.1(TP) ; also on sheet 6
LOSn0: R69.2 U6.14(~{LOS0})
LOSn1: R68.2 U6.37(~{LOS1})
LOSn2: R66.2 U6.36(~{LOS2})
LOSn3: R67.2 U6.13(~{LOS3})
OLDI0_A0N: J4.33 R102.1
OLDI0_A0N_R: J10.8 R109.2
OLDI0_A0P: J4.32 R101.1
OLDI0_A0P_R: J10.9 R110.2
OLDI0_A1N: J4.30 R100.1
OLDI0_A1N_R: J10.11 R108.2
OLDI0_A1P: J4.29 R99.1
OLDI0_A1P_R: J10.12 R107.2
OLDI0_A2N: J4.27 R98.1
OLDI0_A2N_R: J10.14 R106.2
OLDI0_A2P: J4.26 R97.1
OLDI0_A2P_R: J10.15 R105.2
OLDI0_A3N: J4.24 R96.1
OLDI0_A3N_R: J10.20 R104.2
OLDI0_A3P: J4.23 R95.1
OLDI0_A3P_R: J10.21 R103.2
OLDI0_CLKN: J4.21 R112.1
OLDI0_CLKN_R: J10.17 R114.2
OLDI0_CLKP: J4.20 R111.1
OLDI0_CLKP_R: J10.18 R113.2
PE0: R64.2 R65.1 U6.31(PE0)
PE1: R62.2 R63.1 U6.20(PE1)
PE2: R60.2 R61.1 U6.19(PE2)
PE3: R53.2 R59.1 U6.18(PE3)
PWDNn: R74.2 U6.38(~{PWDN})
PWDNn0: R73.2 U6.35(~{PWDN0})
PWDNn1: R72.2 U6.34(~{PWDN1})
PWDNn2: R71.2 U6.33(~{PWDN2})
PWDNn3: R70.2 U6.32(~{PWDN3})
SOC_I2C1_SCL: J4.15 J9.2 TP28.1(TP)
SOC_I2C1_SDA: J4.14 J9.1 TP27.1(TP)
SOC_SPI1_CLK: J4.9 J11.2
SOC_SPI1_CS0: J4.8 J11.1
SOC_SPI1_MISO: J4.5 J11.3
SOC_SPI1_MOSI: J4.6 J11.4
SOC_WKUP_SCL: J4.18 U1.6(SCL)
SOC_WKUP_SDA: J4.17 U1.5(SDA)
VCOM: C13.1 C19.1 J10.1 TP8.1(TP) ; also on sheet 6
VGH: C17.1 C18.1 J10.38 TP10.1(TP) ; also on sheet 6
VGL: C12.1 C16.1 J10.35 TP9.1(TP) ; also on sheet 6
N18830955: R95.2 U6.1(IN0+)
N18830958: R96.2 U6.2(IN0-)
N18830961: R97.2 U6.4(IN1+)
N18830964: R98.2 U6.5(IN1-)
N18830967: R99.2 U6.6(IN2+)
N18830970: R100.2 U6.7(IN2-)
N18830973: R101.2 U6.9(IN3+)
N18830976: R102.2 U6.10(IN3-)
N18831695: R103.1 U6.29(OUT0+)
N18831698: R104.1 U6.28(OUT0-)
N18831701: R105.1 U6.27(OUT1+)
N18831704: R106.1 U6.26(OUT1-)
N18831707: R107.1 U6.24(OUT2+)
N18831710: R108.1 U6.23(OUT2-)
N18831713: R110.1 U6.22(OUT3+)
N18831716: R109.1 U6.21(OUT3-)
N18844920: R113.1 U7.7(OUT+)
N18844923: R114.1 U7.6(OUT-)
N18844960: R111.2 U7.2(IN+)
N18844963: R112.2 U7.3(IN-)

Not connected (* = marked no-connect by the designer): J10 4* 5* 6* 23* 24* 26* 27* 28* 33* 34* 36* 37*; U6 17(NC)*; U7 1(NC1)* 4(NC2)* 5(NC3)*

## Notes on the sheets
sheet 1
- HARDWARE SCHEMATICS
- STANDOFFs
- M3 X 12 SCREWS
- HEX NUT
- FABRICATED HARDWARE
- M2.5 X 16 SCREWS
- BUMPER CYLINDRICAL
- LABEL
- BARE PCB
- Board Serial No.
- ASSEMBLY NOTES
- 1. All MSL components should be baked as per JEDEC
  standard.
  2. PCB should be baked at 120 degree for 8 hours.
  3. Board assembly must comply with workmanship standards.
  IPC-A-610 Class 2, unless otherwise specified.
  4. These assemblies are ESD sensitive, ESD precautions
  shall be observed.
  5. These assemblies must be clean and free from flux and
  all contaminants. Use of no clean flux is not acceptable.
  6. Provide serial numbers to the assembled boards for
  identification.
  7. The assembled board are wrapped in ESD Covers(individual)
  and
  packed securely before shipment.
- FIDUCIALS
- LOGOs
- Texas Intruments
- For Evaluation only; not FCC approved for resale
- WEEE Mark
- CE Mark
sheet 2
- BLOCK DIAGRAM
sheet 3
- VERSION HISTORY
- VER #
- DATE
- DESCRIPTION OF CHANGES
- AUTHOR
- REVIEWED  BY
- APPROVED BY
- 0.1
- 02nd JULY 2018
- Drafted from "PROC070_OLDI-LCD1EVM_SCH_REV E2" document.
- Mistral Design Team
- AJIT MB
- AJIT MB
- 0.2
- 02nd JULY 2018
- C31,C36 & C38 capacitor package changed to 0805
- Mistral Design Team
- AJIT MB
- AJIT MB
- 1.0
- 03rd JULY 2018
- Baselined
- Mistral Design Team
- AJIT MB
- AJIT MB
sheet 4
- MAXWELL LCD ADAPTER BOARD
- TABLE OF CONTENTS
- REV
- E3
- VER
- 1.0
- PAGE
- CONTENTS
- 01
- TABLE OF CONTENTS
- 02
- REVISION HISTORY
- 03
- BLOCK DIAGRAM
- 04
- LCD CONNECTORS & BOARD ID EEPROM
- 05
- LCD POWER
- 06
- HARDWARE SCHEMATICS
sheet 5
- BOARD ID EEPROM
- LCD CTP CONNECTOR
- SPI HEADER
- LCD FFC CABLE CONNECTOR
            (Main Board)
- LCD MODULE CONNECTOR
- EEPROM slave address is Set by host.
- LVDS BUFFER
- LCD TOUCH TESTPOINTS
